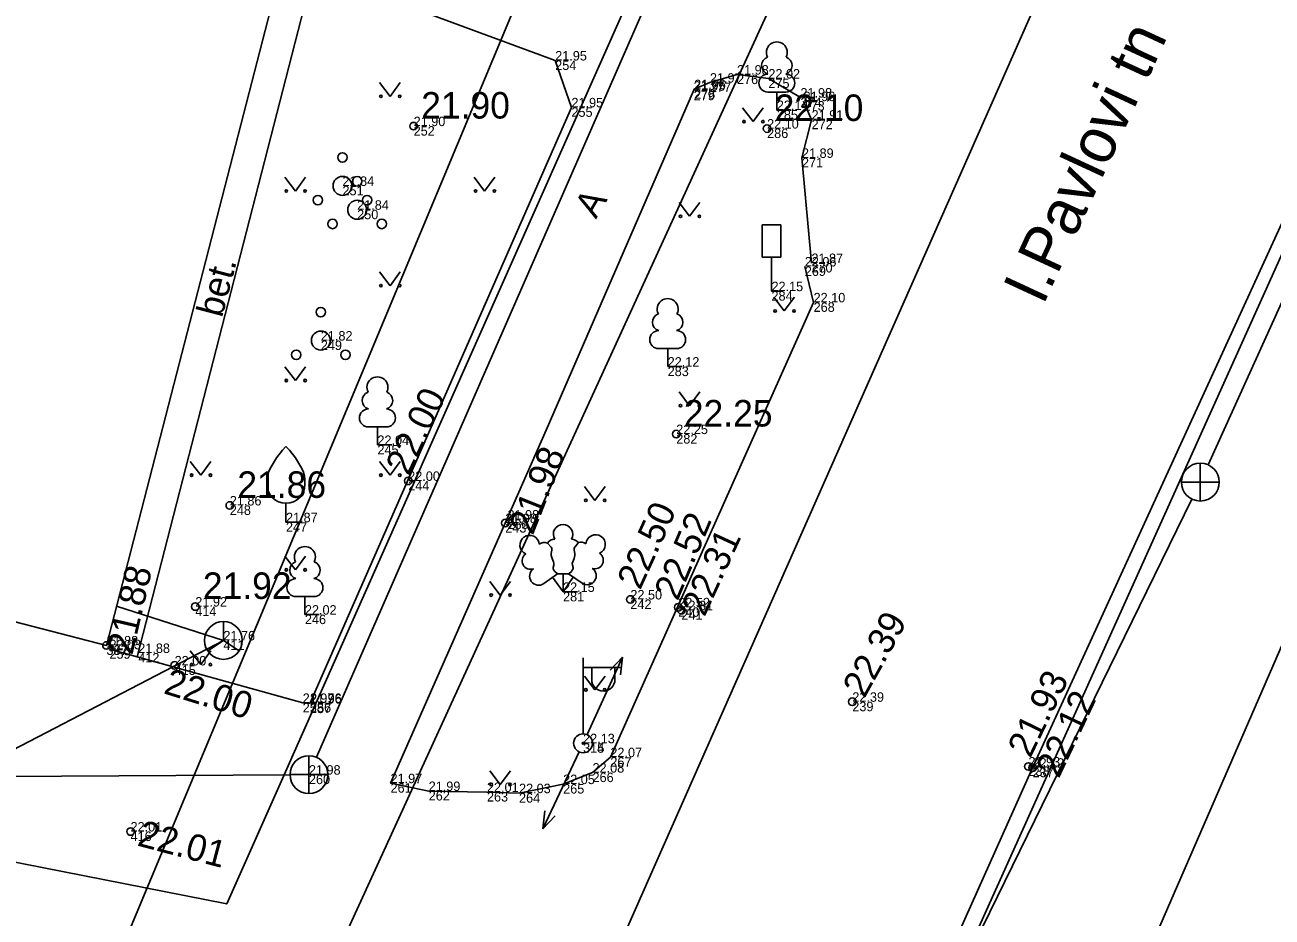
# Model space of a CAD drawing. Extents: x 714279 to 714471, y 6589851 to 6590083.
# Drawn here: x 714372.9 to 714405.84, y 6589972.81 to 6589996.36 of the extents above; entities that cross this region are included whole.
import ezdxf

# ---------------------------------------------------------------- set-up
doc = ezdxf.new("R2010")
doc.units = 0
for name, color, linetype in [('HALJASTUS', 7, 'Continuous'), ('HOONE', 7, 'Continuous'), ('KKAEV', 7, 'Continuous'), ('KORGUS', 7, 'Continuous'), ('KPKAABEL', 7, 'Continuous'), ('KTRASS', 7, 'Continuous'), ('LIIKLUS', 7, 'Continuous'), ('MOOTKORG', 7, 'Continuous'), ('MOOTMPUNKT', 7, 'Continuous'), ('MOOTPIIR', 7, 'Continuous'), ('MPOHULIIN', 7, 'Continuous'), ('PIIR', 7, 'Continuous'), ('POST', 7, 'Continuous'), ('PUU', 7, 'Continuous'), ('SIKAEV', 7, 'Continuous'), ('SITRASS', 7, 'Continuous'), ('SKKAEV', 7, 'Continuous'), ('SKTRASS', 7, 'Continuous'), ('TEE', 7, 'Continuous'), ('VTRASS', 7, 'Continuous')]:
    doc.layers.add(name, color=color, linetype=linetype)

# ---------------------------------------------------------------- blocks, each defined once
blk = doc.blocks.new('RING02_1')
at = {"layer": 'KORGUS'}
blk.add_circle((0, 0), 0.2, dxfattribs=at)
blk = doc.blocks.new('RING02_2')
at = {"layer": 'KORGUS'}
blk.add_circle((0, 0), 0.2, dxfattribs=at)
blk = doc.blocks.new('RING02')
at = {"layer": 'KORGUS'}
blk.add_circle((0, 0), 0.2, dxfattribs=at)
blk = doc.blocks.new('LEHTP1')
at = {"layer": 'PUU'}
for p, q in [((0.48, 0.95), (-0.48, 0.95)), ((0, 0), (0, 0.95)), ((0.76, 0), (0, 0))]:
    blk.add_line(p, q, dxfattribs=at)
for centre, radius, start, end in [((0, 3.04), 0.554, 332.5799, 207.4201), ((-0.34, 2.345), 0.465, 109.02174, 253.14154), ((0.34, 2.345), 0.465, 286.85082, 70.98591), ((-0.475, 1.425), 0.475, 90.0016, 269.3953), ((0.475, 1.425), 0.475, 270.6047, 89.9984)]:
    blk.add_arc(centre, radius, start, end, dxfattribs=at)
blk = doc.blocks.new('VILJA1')
at = {"layer": 'PUU'}
for p, q in [((0, 0), (0, 1)), ((0.8, 0), (0, 0))]:
    blk.add_line(p, q, dxfattribs=at)
for points in [[(-1, 2), (-1, 2.3), (-0.98, 2.43), (-0.91, 2.69), (-0.79, 2.93), (-0.5, 3.4), (-0.18, 3.81), (0, 4)], [(1, 2), (1, 2.3), (0.98, 2.43), (0.91, 2.69), (0.79, 2.93), (0.5, 3.4), (0.18, 3.81), (0, 4)]]:
    blk.add_lwpolyline(points, dxfattribs=at)
blk.add_arc((0, 2), 1, 180, 0, dxfattribs=at)
blk = doc.blocks.new('PQQSAS')
at = {"layer": 'HALJASTUS'}
for centre, radius in [((0, 1.5), 0.25), ((0, 0), 0.5), ((-1.3, -0.75), 0.25), ((1.3, -0.75), 0.25)]:
    blk.add_circle(centre, radius, dxfattribs=at)
blk = doc.blocks.new('KAKAEV')
at = {"layer": 'KKAEV'}
for p, q in [((0, -1), (0, 1)), ((-1, 0), (1, 0))]:
    blk.add_line(p, q, dxfattribs=at)
blk.add_circle((0, 0), 1, dxfattribs=at)
blk = doc.blocks.new('LEHTP3')
at = {"layer": 'PUU'}
for p, q in [((-1.02, 0.44), (-0.3, 0.95)), ((0, 0), (-0.55, 0.77)), ((-0.3, 0.95), (0.29, 0.95)), ((0, 0), (0, 0.95)), ((0, 0), (0.54, 0.78)), ((0.29, 0.95), (1.01, 0.46)), ((0.76, 0), (0, 0))]:
    blk.add_line(p, q, dxfattribs=at)
for points in [[(-0.825, 2.575), (-0.62, 2.37), (-0.59, 2.31), (-0.59, 2.2), (-0.62, 2.02), (-0.62, 1.93), (-0.58, 1.77), (-0.5, 1.59), (-0.48, 1.5), (-0.49, 1.41), (-0.52, 1.28), (-0.52, 1.22), (-0.48, 1.14), (-0.43, 1.08), (-0.3, 0.95)], [(0.808, 2.603), (0.62, 2.37), (0.59, 2.31), (0.59, 2.2), (0.62, 2.02), (0.63, 1.93), (0.59, 1.77), (0.51, 1.59), (0.49, 1.5), (0.5, 1.41), (0.53, 1.28), (0.53, 1.22), (0.49, 1.14), (0.44, 1.08), (0.3, 0.95)]]:
    blk.add_lwpolyline(points, dxfattribs=at)
for centre, radius, start, end in [((0, 3.04), 0.512, 90.00126, 211.01588), ((0, 3.04), 0.512, 328.98412, 89.99874), ((-1.767, 2.474), 0.512, 125.53894, 246.55356), ((-1.767, 2.474), 0.512, 4.5218, 125.53642), ((-0.475, 2.375), 0.403, 84.79647, 150.29947), ((0.475, 2.375), 0.403, 34.38566, 95.20353), ((1.721, 2.506), 0.512, 55.52204, 176.53666), ((1.721, 2.506), 0.512, 294.50491, 55.51952), ((-1.711, 1.64), 0.448, 125.46665, 288.53492), ((-0.994, 2.209), 0.403, 65.23821, 130.74121), ((0.953, 2.227), 0.403, 50.31726, 111.13512), ((1.68, 1.671), 0.448, 252.52354, 55.59181), ((-1.292, 0.828), 0.475, 125.53768, 305.53661), ((1.277, 0.852), 0.475, 235.52186, 55.52078)]:
    blk.add_arc(centre, radius, start, end, dxfattribs=at)
blk = doc.blocks.new('LIIKLM')
at = {"layer": 'LIIKLUS'}
for p, q in [((-0.5, 3.5), (-0.5, 1.8)), ((0.5, 3.5), (-0.5, 3.5)), ((0.5, 3.5), (0.5, 1.8)), ((0.5, 1.8), (-0.5, 1.8)), ((0, 1.8), (0, 0)), ((0.5, 0), (0, 0))]:
    blk.add_line(p, q, dxfattribs=at)
blk = doc.blocks.new('POINT_DISPLAY')
blk.add_line((0, 0), (0, 0))
blk = doc.blocks.new('VAPOST')
at = {"layer": 'POST'}
for p, q in [((0, 0.5), (0, 4.5)), ((0, 4), (2, 4)), ((0.453, 3.358), (0.453, 4)), ((1.679, 3.358), (1.679, 4))]:
    blk.add_line(p, q, dxfattribs=at)
blk.add_arc((1.066, 3.358), 0.613, 180, 0, dxfattribs=at)
blk.add_blockref('POINT_DISPLAY', (0, 0), dxfattribs=at)
blk = doc.blocks.new('BEPOST')
at = {"layer": 'POST'}
for radius in [0.5, 0.0467]:
    blk.add_circle((0, 0), radius, dxfattribs=at)
blk = doc.blocks.new('MPSUUN')
at = {"layer": 'MPOHULIIN'}
for p, q in [((0.5, 0), (5, 0)), ((5, 0), (4.097, -0.297)), ((5, 0), (4.098, 0.3))]:
    blk.add_line(p, q, dxfattribs=at)
blk.add_blockref('POINT_DISPLAY', (0, 0), dxfattribs=at)
blk = doc.blocks.new('SIKAEV')
at = {"layer": 'SIKAEV'}
for p, q in [((0, 1), (0, 0)), ((0, 0), (-0.83, -0.55)), ((0, 0), (0.83, -0.55))]:
    blk.add_line(p, q, dxfattribs=at)
blk.add_circle((0, 0), 1, dxfattribs=at)
blk = doc.blocks.new('MURU_1')
at = {"layer": 'HALJASTUS'}
for p, q in [((-0.93, 1.21), (0, 0)), ((0, 0), (0.89, 1.21))]:
    blk.add_line(p, q, dxfattribs=at)
for centre in [(-0.8, 0), (0.86, 0)]:
    blk.add_circle(centre, 0.11, dxfattribs=at)

msp = doc.modelspace()

# ---------------------------------------------------------------- linework, layer by layer
at = {"layer": 'HOONE'}
msp.add_lwpolyline([(714368.084, 6590003.497), (714362.833, 6589983.153), (714366.948, 6589982.091), (714366.479, 6589980.273), (714368.704, 6589979.699), (714369.168, 6589981.497), (714375.054, 6589979.978), (714385.707, 6590021.254), (714379.88, 6590022.758), (714380.346, 6590024.563), (714378.09, 6590025.145), (714377.63, 6590023.366), (714373.521, 6590024.426), (714369.05, 6590007.103), (714363.815, 6590008.455), (714364.534, 6590011.243), (714349.394, 6590015.151), (714346.235, 6590002.913), (714361.396, 6589999), (714362.901, 6590004.835), (714368.084, 6590003.497)], dxfattribs=at)
at = {"layer": 'KORGUS'}
msp.add_circle((714375.053, 6589979.976), 0.1, dxfattribs=at)
at = {"layer": 'KPKAABEL'}
msp.add_lwpolyline([(714396.776, 6589958.555), (714410.513, 6589990.138), (714421.117, 6590017.14), (714434.01, 6590042.696)], dxfattribs=at)
at = {"layer": 'KTRASS'}
for points in [[(714380.6, 6589977.024), (714399.521, 6590020.255)], [(714352.737, 6589976.407), (714379.9, 6589976.563)]]:
    msp.add_lwpolyline(points, dxfattribs=at)
at = {"layer": 'MOOTPIIR'}
msp.add_lwpolyline([(714325.392, 6590064.148), (714418.405, 6590047.495), (714428.059, 6590039.059), (714392.952, 6589961.13), (714372.822, 6589966.903), (714302.696, 6589965.199), (714319.941, 6590042.637), (714325.392, 6590064.148)], dxfattribs=at)
at = {"layer": 'PIIR'}
msp.add_lwpolyline([(714313.433, 6589985.9), (714378.228, 6589973.152), (714405.629, 6590034.791), (714332.408, 6590052.951), (714332.595, 6590052.951)], dxfattribs=at)
at = {"layer": 'SITRASS'}
for points in [[(714403.003, 6590037.966), (714373.288, 6589966.766)], [(714345.596, 6589963.208), (714378.141, 6589980.11), (714375.32, 6589981.011)]]:
    msp.add_lwpolyline(points, dxfattribs=at)
at = {"layer": 'SKKAEV'}
for p, q in [((714403.941, 6589983.789), (714403.941, 6589984.789)), ((714403.441, 6589984.289), (714404.441, 6589984.289))]:
    msp.add_line(p, q, dxfattribs=at)
msp.add_circle((714403.941, 6589984.289), 0.5, dxfattribs=at)
at = {"layer": 'SKTRASS'}
for points in [[(714404.146, 6589984.744), (714419.399, 6590018.407)], [(714392.66, 6589961.24), (714403.716, 6589983.842)]]:
    msp.add_lwpolyline(points, dxfattribs=at)
at = {"layer": 'TEE'}
for points in [[(714428.059, 6590039.059), (714427.912, 6590038.899), (714421.383, 6590024.973), (714411.21, 6590002.295), (714399.51, 6589976.749), (714392.577, 6589961.261), (714392.577, 6589961.261)], [(714375.863, 6589979.673), (714380.355, 6589997.141)], [(714382.534, 6589997.039), (714386.904, 6589995.418), (714387.333, 6589994.181), (714380.429, 6589978.462)], [(714393.38, 6589994.439), (714392.534, 6589994.942), (714391.706, 6589995.045), (714390.99, 6589994.833), (714390.574, 6589994.66), (714390.56, 6589994.62), (714386.667, 6589985.657), (714382.555, 6589976.341), (714383.563, 6589976.134), (714385.102, 6589976.107), (714385.949, 6589976.077), (714387.114, 6589976.317), (714387.89, 6589976.62), (714388.361, 6589977.027), (714393.728, 6589989.033), (714393.495, 6589989.981)], [(714393.67, 6589990.072), (714393.421, 6589992.847), (714393.675, 6589993.855), (714393.463, 6589994.345)], [(714380.429, 6589978.44), (714380.235, 6589978.459), (714375.132, 6589979.876)]]:
    msp.add_lwpolyline(points, dxfattribs=at)
at = {"layer": 'VTRASS'}
for points in [[(714378.183, 6589965.384), (714401.816, 6590016.993), (714414.734, 6590044.36), (714416.367, 6590047.881)], [(714384.776, 6589963.41), (714420.935, 6590045.157)]]:
    msp.add_lwpolyline(points, dxfattribs=at)

# ---------------------------------------------------------------- block references
at = {"layer": 'HALJASTUS'}
for name, p, xscale, yscale in [('MURU_1', (714382.541, 6589994.472), 0.3, 0.3), ('MURU_1', (714392.131, 6589993.806), 0.3, 0.3), ('PQQSAS', (714381.286, 6589992.108), 0.5, 0.5), ('MURU_1', (714380.041, 6589991.972), 0.3, 0.3), ('PQQSAS', (714381.674, 6589991.478), 0.5, 0.5), ('MURU_1', (714385.041, 6589991.972), 0.3, 0.3), ('MURU_1', (714390.453, 6589991.306), 0.3, 0.3), ('MURU_1', (714382.541, 6589989.472), 0.3, 0.3), ('MURU_1', (714392.953, 6589988.806), 0.3, 0.3), ('PQQSAS', (714380.714, 6589988.025), 0.5, 0.5), ('MURU_1', (714380.041, 6589986.972), 0.3, 0.3), ('MURU_1', (714390.453, 6589986.306), 0.3, 0.3), ('MURU_1', (714377.541, 6589984.472), 0.3, 0.3), ('MURU_1', (714382.541, 6589984.472), 0.3, 0.3), ('MURU_1', (714387.953, 6589983.806), 0.3, 0.3), ('MURU_1', (714380.041, 6589981.972), 0.3, 0.3), ('MURU_1', (714385.453, 6589981.306), 0.3, 0.3), ('MURU_1', (714377.541, 6589979.472), 0.3, 0.3), ('MURU_1', (714387.953, 6589978.806), 0.3, 0.3), ('MURU_1', (714385.453, 6589976.306), 0.3, 0.3)]:
    msp.add_blockref(name, p, dxfattribs=dict(at, xscale=xscale, yscale=yscale))
at = {"layer": 'KKAEV', "xscale": 0.5, "yscale": 0.5}
msp.add_blockref('KAKAEV', (714380.4, 6589976.566), dxfattribs=at)
at = {"layer": 'KORGUS', "xscale": 0.5, "yscale": 0.5}
for name, p in [('RING02', (714383.165, 6589993.685)), ('RING02', (714392.5, 6589993.621)), ('RING02', (714390.101, 6589985.556)), ('RING02_1', (714383.022, 6589984.321)), ('RING02', (714378.31, 6589983.672)), ('RING02_1', (714385.585, 6589983.206)), ('RING02', (714377.399, 6589981.004)), ('RING02', (714388.889, 6589981.19)), ('RING02_1', (714390.154, 6589980.983)), ('RING02_2', (714390.237, 6589980.907)), ('RING02_2', (714376.853, 6589979.449)), ('RING02_1', (714394.751, 6589978.49)), ('RING02_2', (714399.402, 6589976.781)), ('RING02_1', (714399.51, 6589976.749)), ('RING02_1', (714375.689, 6589975.065))]:
    msp.add_blockref(name, p, dxfattribs=at)
at = {"layer": 'LIIKLUS', "xscale": 0.5, "yscale": 0.5}
msp.add_blockref('LIIKLM', (714392.616, 6589989.329), dxfattribs=at)
at = {"layer": 'MPOHULIIN', "xscale": 0.49999999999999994}
for yscale, rotation in [(0.49999999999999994, 65.42608535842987), (0.5000000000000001, -115.26766566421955)]:
    msp.add_blockref('MPSUUN', (714387.641, 6589977.396), dxfattribs=dict(at, yscale=yscale, rotation=rotation))
at = {"layer": 'POST', "xscale": 0.5, "yscale": 0.5}
for name, p in [('VAPOST', (714387.641, 6589977.396)), ('BEPOST', (714387.641, 6589977.394))]:
    msp.add_blockref(name, p, dxfattribs=at)
at = {"layer": 'PUU', "xscale": 0.5, "yscale": 0.5}
for name, p in [('LEHTP1', (714392.757, 6589994.11)), ('LEHTP1', (714389.874, 6589987.337)), ('LEHTP1', (714382.209, 6589985.269)), ('VILJA1', (714379.794, 6589983.229)), ('LEHTP3', (714387.111, 6589981.39)), ('LEHTP1', (714380.294, 6589980.79))]:
    msp.add_blockref(name, p, dxfattribs=at)
at = {"layer": 'SIKAEV', "xscale": 0.5, "yscale": 0.5}
msp.add_blockref('SIKAEV', (714378.141, 6589980.11), dxfattribs=at)

# ---------------------------------------------------------------- texts
at = {"layer": 'KORGUS'}
for s, p in [('21.90', (714383.365, 6589993.885)), ('22.10', (714392.7, 6589993.821)), ('22.25', (714390.301, 6589985.756)), ('21.86', (714378.51, 6589983.872)), ('21.92', (714377.599, 6589981.204))]:
    msp.add_text(s, height=0.7, dxfattribs=at).set_placement(p)
for s, rotation, p in [('22.00', 64.7681, (714383.029, 6589984.435)), ('21.98', 68.3572, (714386.311, 6589982.864)), ('22.50', 65.5217, (714389.147, 6589981.418)), ('22.52', 67.0311, (714390.137, 6589981.131)), ('22.31', 65.2334, (714390.847, 6589980.711)), ('21.88', 76.932, (714375.734, 6589979.704)), ('22.39', 60.8752, (714395.071, 6589978.563)), ('22.00', 342.6396, (714376.535, 6589978.719)), ('21.93', 63.9611, (714399.45, 6589976.982)), ('22.12', 64.6718, (714400.202, 6589976.442)), ('22.01', 345.168, (714375.84, 6589974.7))]:
    msp.add_text(s, height=0.7, rotation=rotation, dxfattribs=at).set_placement(p)
at = {"layer": 'MOOTKORG'}
for s, p in [('21.95', (714386.904, 6589995.418)), ('21.98', (714391.706, 6589995.045)), ('21.97', (714390.99, 6589994.833)), ('22.02', (714392.534, 6589994.942)), ('21.95', (714390.56, 6589994.62)), ('21.96', (714390.574, 6589994.66)), ('21.98', (714393.38, 6589994.439)), ('21.95', (714387.333, 6589994.181)), ('22.14', (714392.757, 6589994.11)), ('21.96', (714393.463, 6589994.345)), ('21.91', (714393.675, 6589993.855)), ('21.90', (714383.165, 6589993.685)), ('22.10', (714392.5, 6589993.621)), ('21.89', (714393.421, 6589992.847)), ('21.84', (714381.286, 6589992.108)), ('21.84', (714381.674, 6589991.478)), ('21.87', (714393.67, 6589990.072)), ('22.06', (714393.495, 6589989.981)), ('22.15', (714392.616, 6589989.329)), ('22.10', (714393.728, 6589989.033)), ('21.82', (714380.714, 6589988.025)), ('22.12', (714389.874, 6589987.337)), ('22.25', (714390.101, 6589985.556)), ('22.04', (714382.209, 6589985.269)), ('22.00', (714383.022, 6589984.321)), ('21.86', (714378.31, 6589983.672)), ('21.87', (714379.794, 6589983.229)), ('21.98', (714385.585, 6589983.206)), ('21.98', (714385.643, 6589983.3)), ('22.15', (714387.111, 6589981.39)), ('22.50', (714388.889, 6589981.19)), ('21.92', (714377.399, 6589981.004)), ('22.52', (714390.154, 6589980.983)), ('22.31', (714390.237, 6589980.907)), ('22.02', (714380.294, 6589980.79)), ('21.88', (714375.053, 6589979.976)), ('22.03', (714375.132, 6589979.876)), ('21.76', (714378.141, 6589980.11)), ('21.88', (714375.893, 6589979.778)), ('22.00', (714376.853, 6589979.449)), ('21.97', (714380.235, 6589978.459)), ('21.96', (714380.429, 6589978.462)), ('21.96', (714380.429, 6589978.44)), ('22.39', (714394.751, 6589978.49)), ('22.13', (714387.641, 6589977.396)), ('22.13', (714387.641, 6589977.394)), ('22.07', (714388.361, 6589977.027)), ('21.98', (714380.4, 6589976.566)), ('22.08', (714387.89, 6589976.62)), ('21.93', (714399.402, 6589976.781)), ('22.12', (714399.51, 6589976.749)), ('21.97', (714382.555, 6589976.341)), ('22.05', (714387.114, 6589976.317)), ('21.99', (714383.563, 6589976.134)), ('22.01', (714385.102, 6589976.107)), ('22.03', (714385.949, 6589976.077)), ('22.01', (714375.689, 6589975.065))]:
    msp.add_text(s, height=0.25, dxfattribs=at).set_placement(p)
at = {"layer": 'MOOTMPUNKT'}
for s, p in [('254', (714386.904, 6589995.168)), ('276', (714391.706, 6589994.795)), ('275', (714392.534, 6589994.692)), ('279', (714390.56, 6589994.37)), ('278', (714390.574, 6589994.41)), ('277', (714390.99, 6589994.583)), ('274', (714393.38, 6589994.189)), ('273', (714393.463, 6589994.095)), ('255', (714387.333, 6589993.931)), ('285', (714392.757, 6589993.86)), ('252', (714383.165, 6589993.435)), ('286', (714392.5, 6589993.371)), ('272', (714393.675, 6589993.605)), ('271', (714393.421, 6589992.597)), ('251', (714381.286, 6589991.858)), ('250', (714381.674, 6589991.228)), ('270', (714393.67, 6589989.822)), ('269', (714393.495, 6589989.731)), ('284', (714392.616, 6589989.079)), ('268', (714393.728, 6589988.783)), ('249', (714380.714, 6589987.775)), ('283', (714389.874, 6589987.087)), ('282', (714390.101, 6589985.306)), ('245', (714382.209, 6589985.019)), ('244', (714383.022, 6589984.071)), ('248', (714378.31, 6589983.422)), ('247', (714379.794, 6589982.979)), ('243', (714385.585, 6589982.956)), ('280', (714385.643, 6589983.05)), ('281', (714387.111, 6589981.14)), ('242', (714388.889, 6589980.94)), ('414', (714377.399, 6589980.754)), ('246', (714380.294, 6589980.54)), ('240', (714390.154, 6589980.733)), ('241', (714390.237, 6589980.657)), ('387', (714375.053, 6589979.726)), ('259', (714375.132, 6589979.626)), ('411', (714378.141, 6589979.86)), ('412', (714375.893, 6589979.528)), ('415', (714376.853, 6589979.199)), ('239', (714394.751, 6589978.24)), ('258', (714380.235, 6589978.209)), ('256', (714380.429, 6589978.212)), ('257', (714380.429, 6589978.19)), ('314', (714387.641, 6589977.146)), ('315', (714387.641, 6589977.144)), ('267', (714388.361, 6589976.777)), ('260', (714380.4, 6589976.316)), ('266', (714387.89, 6589976.37)), ('238', (714399.402, 6589976.531)), ('237', (714399.51, 6589976.499)), ('261', (714382.555, 6589976.091)), ('265', (714387.114, 6589976.067)), ('262', (714383.563, 6589975.884)), ('263', (714385.102, 6589975.857)), ('264', (714385.949, 6589975.827)), ('416', (714375.689, 6589974.815))]:
    msp.add_text(s, height=0.25, dxfattribs=at).set_placement(p)
at = {"layer": 'TEE'}
for s, height, rotation, p in [('I.Pavlovi tn', 1.2, 65.1792, (714399.788, 6589988.93)), ('A', 0.7, 59.6306, (714387.98, 6589991.216)), ('bet.', 0.7, 75.3291, (714378.103, 6589988.609))]:
    msp.add_text(s, height=height, rotation=rotation, dxfattribs=at).set_placement(p)

doc.saveas('drawing.dxf')
